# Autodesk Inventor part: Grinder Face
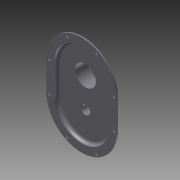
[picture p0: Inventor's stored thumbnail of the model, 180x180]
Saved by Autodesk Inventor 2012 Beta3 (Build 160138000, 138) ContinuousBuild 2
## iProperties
Created: 2010-12
Part Number: Grinder Face
Document SubType Name: Modeling
Designer: Thom Tremblay
Density: 7.25 g/cm^3
Material: Cast Iron
Mass: 515.624 g
Surface Area: 438.513 cm^2
Volume: 71.1205 cm^3
Author: Thom Tremblay
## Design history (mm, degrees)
sketch "Sketch1"
  geometry: L1 (-50, -50)-(-50, 0); L2 (50, 0)-(50, -50); L3 (-60, 0)-(-60, -50); L4 (60, -50)-(60, 0); A1 r 50 centre (0, 0) between (50, 0) and (-50, 0); A2 r 50 centre (0, -50) between (-50, -50) and (50, -50); A3 r 60 centre (0, -50) between (-60, -50) and (60, -50); A4 r 60 centre (0, 0) between (60, 0) and (-60, 0); 1 further point
  constraints: 8 end point, 8 point on circle, 4 centre point, 4 tangent, 2 parallel, 1 coincident, 1 vertical, 3 other
  dimensions: "d0" = 50 distance of L2.start L2.end; "d1" = 50 radius of A1; "d2" = 10 radial gap between concentric circles of A4 A1
extrude "Extrusion1" new body sketch "Sketch1" distance "d3" = 10; taper "d4" = -2 deg
extrude "Extrusion2" join sketch "Sketch1" distance "d5" = 3; taper "d6" = -2 deg
fillet "Fillet1" dims "d7" = 8
shell "Shell2" dims "d128" = 3
fillet "Fillet2" dims "d9" = 1.5, "d10" = 1
sketch "Sketch7"
  geometry: C1 r 22.5 at (0, 0); 1 further point
  constraints: 1 centre point, 1 coincident
  dimensions: "d63" = 45 diameter of C1
extrude "Extrusion8" join sketch "Sketch7" distance "d64" = 19; taper "d65" = -2 deg
hole "Hole3" diameter "d68" = 35; stored, may be unused: countersink angle "d72" = 82 deg, drill point angle "d74" = 118 deg; dims "d66" = 10, "d67" = 10, "d69" = 19.05, "d70" = 9.525, "d71" = 6.35, "d73" = 25.4
fillet "Fillet11" dims "d75" = 3
sketch "Sketch8"
  geometry: C1 r 12.5 at (0, -50); A1 r 60 centre (0, -50) between (-60, -50) and (60, -50) reference; 1 further point
  constraints: 1 centre point, 1 coincident
  dimensions: "d76" = 25 diameter of C1
extrude "Extrusion9" join sketch "Sketch8" distance "d77" = 12; taper "d78" = -2 deg; dims "d89" = 8, "d90" = -2 deg
fillet "Fillet12" dims "d79" = 3
hole "Hole4" diameter "d82" = 14; stored, may be unused: countersink angle "d86" = 82 deg, drill point angle "d88" = 118 deg; dims "d80" = 10, "d81" = 10, "d83" = 19.05, "d84" = 9.525, "d85" = 6.35, "d87" = 8
sketch "Sketch9" dims "d91" = 45
  geometry: L1 (0, 0)-(0, 22.5); C1 r 4 at (0, 22.5); 1 further point
  constraints: 2 end point, 1 centre point, 1 coincident, 1 vertical, 1 vertical alignment, 2 other
  dimensions: "d92" = 8 diameter of C1
extrude "Extrusion10" join sketch "Sketch9" stored distance "d95" = 0; taper "d96" = 2 deg
fillet "Fillet13" dims "d97" = 3
hole "Hole5" diameter "d100" = 3.242; stored, may be unused: countersink angle "d104" = 82 deg, drill point angle "d106" = 118 deg; dims "d98" = 10, "d99" = 10, "d101" = 8, "d102" = 9.525, "d103" = 6.35, "d105" = 10
pattern_circular "Circular Pattern1" dims "d108" = 360 deg
sketch "Sketch10"
  geometry: L1 (-55, -50.8)-(-55, 0); L2 (55, 0)-(55, -50.8); A1 r 55 centre (0, 0) between (55, 0) and (-55, 0); A2 r 55 centre (0, -50.8) between (-55, -50.8) and (55, -50.8); 9 further points
  constraints: 8 point on circle, 5 coincident, 4 end point, 4 tangent, 2 centre point, 2 horizontal alignment, 2 vertical alignment, 1 parallel, 1 vertical
  dimensions: "d118" = 55 radius of A1; "d120" = 50 distance of point (25, 48.99) point (-25, 48.99)
hole "Hole7" sketch "Sketch10" at (-55, -50.8), (-55, 0), (-25, 48.99), (25, 48.99), (55, 0), (55, -50.8), (25, -99.79), (-25, -99.79) diameter "d121" = 4.5; stored, may be unused: countersink angle "d125" = 82 deg, drill point angle "d127" = 118 deg; dims "d122" = 19.05, "d123" = 7.0866, "d124" = 6.35, "d126" = 25.4
chamfer "Chamfer1" distance "d129" = 1; stored, may be unused: second distance "d130" = 2, angle "d131" = 45 deg
body "Solid1"
